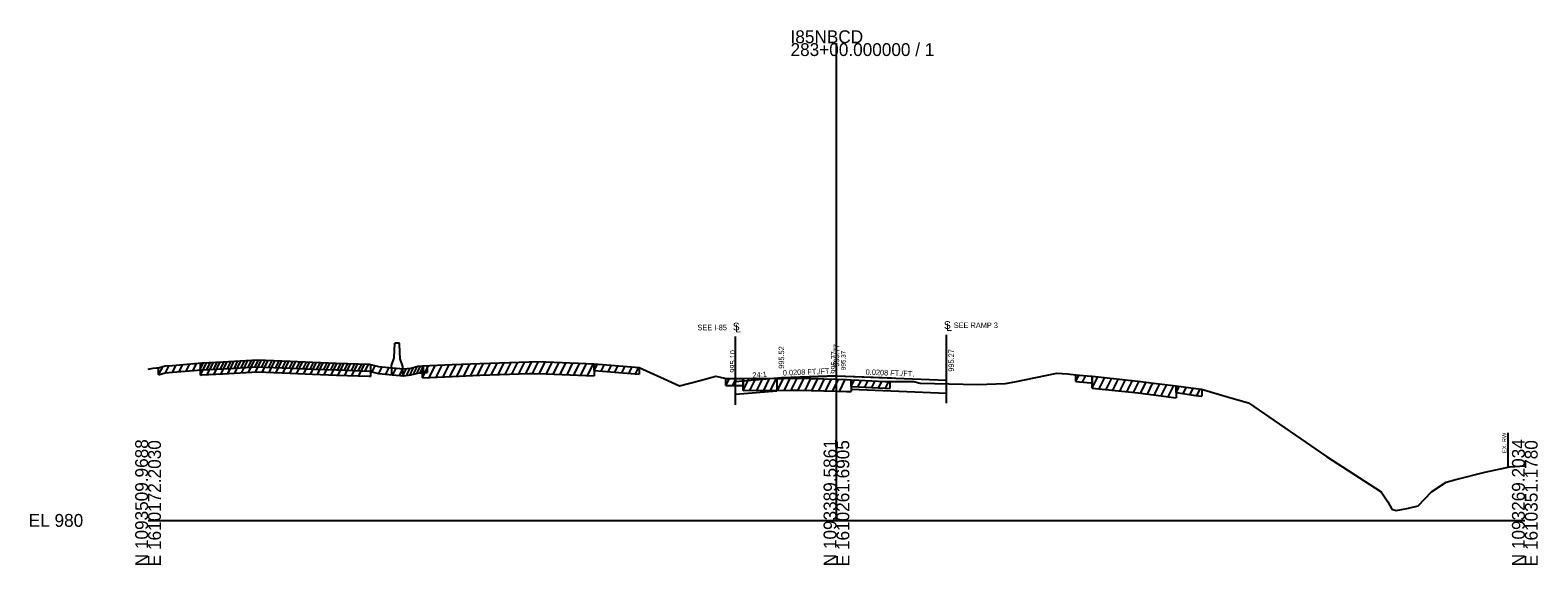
# Model space of a CAD drawing. Extents: x -26 to 1615432, y -20 to 1281970.
# Drawn here: x 974.3 to 1302.8, y 9490.3 to 9606.9 of the extents above; entities that cross this region are included whole.
import ezdxf

# ---------------------------------------------------------------- set-up
doc = ezdxf.new("R2010")
doc.units = 0
for name, color, linetype in [('CLS_MSE_MS_Wall', 7, 'Continuous'), ('CLS_Slope_MSE', 7, 'Continuous'), ('HY_DR_DumbNodes', 7, 'Continuous'), ('RD_EX_Misc', 7, 'Continuous'), ('RD_GPK_XS_Cell', 7, 'Continuous'), ('RD_PD_DR_FlowCtrl', 7, 'Continuous'), ('RD_Sketch1', 7, 'Continuous'), ('RD_XE_Ground', 7, 'Continuous'), ('RD_XS_Base', 7, 'Continuous'), ('RD_XS_ExGround', 7, 'Continuous'), ('RD_XS_ExPaveRet', 7, 'Continuous'), ('RD_XS_MatchLine', 7, 'Continuous'), ('RD_XS_Pave', 7, 'Continuous'), ('RD_XS_PaveShd', 7, 'Continuous'), ('RD_XS_TX_Elev_EX', 7, 'Continuous'), ('RD_XS_TX_Elev_PR', 7, 'Continuous'), ('RD_XS_TX_MatchLine', 7, 'Continuous'), ('RD_XS_TX_ShdSlope', 7, 'Continuous'), ('RD_XS_TX_Slope', 7, 'Continuous')]:
    doc.layers.add(name, color=color, linetype=linetype)

msp = doc.modelspace()

# ---------------------------------------------------------------- linework, layer by layer
at = {"layer": 'CLS_Slope_MSE'}
msp.add_line((1296.33, 9519.09), (1296.33, 9511.57), dxfattribs=at)
at = {"layer": 'HY_DR_DumbNodes'}
for p, q in [((1138, 9531.04), (1150, 9531.54)), ((1150, 9531.54), (1162, 9531.04))]:
    msp.add_line(p, q, dxfattribs=at)
at = {"layer": 'RD_EX_Misc'}
for p, q in [((1097.24, 9532.64), (1097.24, 9534.14)), ((1002.31, 9531.73), (1002.31, 9533.23)), ((1002.31, 9531.73), (1003.75, 9532.16)), ((1003.75, 9532.16), (1005.32, 9532.29)), ((1005.32, 9532.29), (1011.72, 9532.82)), ((1011.72, 9532.82), (1016.31, 9533.06)), ((1016.31, 9533.06), (1023.87, 9533.5)), ((1023.87, 9533.5), (1030.97, 9533.17)), ((1030.97, 9533.17), (1035.84, 9532.96)), ((1035.84, 9532.96), (1041.04, 9532.79)), ((1041.04, 9532.79), (1048.16, 9532.52)), ((1048.16, 9532.52), (1050.23, 9532.02)), ((1050.23, 9532.02), (1053.28, 9531.76)), ((1053.03, 9533.28), (1053.03, 9531.78)), ((1053.03, 9531.78), (1053.28, 9531.76)), ((1053.28, 9531.76), (1055.64, 9531.5)), ((1055.55, 9531.51), (1055.55, 9533.01)), ((1055.55, 9531.51), (1055.64, 9531.5)), ((1055.64, 9531.5), (1057.24, 9531.7)), ((1057.24, 9531.7), (1058.75, 9532.1)), ((1058.75, 9532.1), (1059.79, 9532.18)), ((1059.79, 9533.68), (1059.79, 9532.18)), ((1059.79, 9532.18), (1060.81, 9532.22)), ((1059.79, 9532.18), (1060.05, 9532.19)), ((1060.05, 9532.19), (1060.05, 9533.69)), ((1060.81, 9533.72), (1060.81, 9532.22)), ((1097.24, 9532.64), (1100.85, 9532.35)), ((1100.85, 9532.35), (1107.04, 9531.86)), ((1107.04, 9533.36), (1107.04, 9531.86)), ((1125.93, 9529.41), (1125.93, 9530.91)), ((1129.64, 9530.91), (1129.64, 9529.41)), ((1202.13, 9530.24), (1202.13, 9531.74)), ((1205.76, 9531.44), (1205.76, 9529.94)), ((1125.93, 9529.41), (1127.4, 9529.41)), ((1127.4, 9529.41), (1129.64, 9529.41)), ((1153.19, 9529.16), (1153.19, 9530.66)), ((1153.19, 9529.16), (1154.85, 9529.09)), ((1154.85, 9529.09), (1160.54, 9528.81)), ((1160.54, 9528.81), (1161.67, 9528.76)), ((1161.67, 9530.26), (1161.67, 9528.76)), ((1161.67, 9528.76), (1161.67, 9528.76)), ((1202.13, 9530.24), (1205.41, 9529.97)), ((1205.41, 9529.97), (1205.76, 9529.94)), ((1205.76, 9529.94), (1205.76, 9529.94)), ((1224.05, 9527.85), (1224.05, 9529.35)), ((1224.05, 9527.85), (1228.33, 9527.24)), ((1229.59, 9528.57), (1229.59, 9527.07)), ((1228.33, 9527.24), (1228.86, 9527.17)), ((1228.86, 9527.17), (1229.58, 9527.07)), ((1229.58, 9527.07), (1229.59, 9527.07))]:
    msp.add_line(p, q, dxfattribs=at)
at = {"layer": 'RD_GPK_XS_Cell'}
for p, q in [((1150, 9500), (1150, 9604.02)), ((1000, 9500), (1150, 9500)), ((1150, 9500), (1300, 9500))]:
    msp.add_line(p, q, dxfattribs=at)
at = {"layer": 'RD_PD_DR_FlowCtrl'}
for p, q in [((1138, 9531.04), (1150, 9531.54)), ((1150, 9531.54), (1162, 9531.04))]:
    msp.add_line(p, q, dxfattribs=at)
at = {"layer": 'RD_Sketch1'}
for p, q in [((1008.31, 9532.54), (1009.09, 9534.1)), ((1009.81, 9532.66), (1010.59, 9534.23)), ((1011.31, 9532.79), (1012.09, 9534.34)), ((1012.81, 9532.88), (1013.58, 9534.42)), ((1014.31, 9532.96), (1015.08, 9534.5)), ((1015.81, 9533.04), (1016.58, 9534.58)), ((1017.31, 9533.12), (1018.09, 9534.67)), ((1018.81, 9533.21), (1019.59, 9534.75)), ((1020.31, 9533.3), (1021.09, 9534.84)), ((1021.81, 9533.38), (1022.59, 9534.93)), ((1023.31, 9533.47), (1024.07, 9534.99)), ((1024.81, 9533.46), (1025.55, 9534.92)), ((1026.31, 9533.39), (1027.05, 9534.85)), ((1027.81, 9533.32), (1028.55, 9534.78)), ((1029.31, 9533.25), (1030.05, 9534.71)), ((1030.81, 9533.18), (1031.55, 9534.65)), ((1032.31, 9533.11), (1033.05, 9534.58)), ((1033.81, 9533.05), (1034.55, 9534.52)), ((1035.31, 9532.98), (1036.05, 9534.45)), ((1036.81, 9532.93), (1037.55, 9534.4)), ((1038.31, 9532.88), (1039.05, 9534.35)), ((1039.81, 9532.83), (1040.55, 9534.3)), ((1041.31, 9532.78), (1042.05, 9534.25)), ((1042.81, 9532.72), (1043.55, 9534.19)), ((1044.31, 9532.66), (1045.05, 9534.13)), ((1045.81, 9532.61), (1046.55, 9534.08)), ((1047.31, 9532.55), (1048.05, 9534.02)), ((1097.24, 9532.64), (1097.96, 9534.08)), ((1002.31, 9531.73), (1003.19, 9533.49)), ((1003.81, 9532.16), (1004.6, 9533.73)), ((1005.31, 9532.29), (1006.09, 9533.86)), ((1006.81, 9532.42), (1007.59, 9533.98)), ((1048.81, 9532.36), (1049.48, 9533.7)), ((1050.31, 9532.01), (1051.03, 9533.45)), ((1051.81, 9531.88), (1052.53, 9533.32)), ((1053.31, 9531.76), (1054.03, 9533.18)), ((1054.81, 9531.59), (1055.53, 9533.01)), ((1055.55, 9531.51), (1056.34, 9533.09)), ((1056.31, 9531.58), (1057.11, 9533.18)), ((1057.05, 9531.67), (1057.9, 9533.37)), ((1057.81, 9531.85), (1058.68, 9533.58)), ((1058.55, 9532.04), (1059.35, 9533.64)), ((1059.31, 9532.14), (1060.09, 9533.69)), ((1098.74, 9532.52), (1099.46, 9533.96)), ((1100.24, 9532.4), (1100.96, 9533.85)), ((1101.74, 9532.28), (1102.46, 9533.73)), ((1103.24, 9532.16), (1103.96, 9533.61)), ((1104.74, 9532.04), (1105.46, 9533.49)), ((1106.24, 9531.93), (1106.96, 9533.37)), ((1125.93, 9529.41), (1126.68, 9530.91)), ((1127.43, 9529.41), (1128.18, 9530.91)), ((1202.13, 9530.24), (1202.85, 9531.68)), ((1203.63, 9530.12), (1204.35, 9531.56)), ((1153.19, 9529.16), (1153.93, 9530.63)), ((1154.69, 9529.1), (1155.43, 9530.57)), ((1156.19, 9529.03), (1156.93, 9530.49)), ((1157.69, 9528.95), (1158.43, 9530.42)), ((1159.2, 9528.88), (1159.93, 9530.34)), ((1160.7, 9528.8), (1161.43, 9530.27)), ((1224.05, 9527.85), (1224.75, 9529.25)), ((1225.55, 9527.64), (1226.25, 9529.04)), ((1227.05, 9527.42), (1227.75, 9528.82)), ((1228.55, 9527.21), (1229.26, 9528.62))]:
    msp.add_line(p, q, dxfattribs=at)
at = {"layer": 'RD_XE_Ground'}
for p, q in [((1053.62, 9535.45), (1053.78, 9538.61)), ((1054.8, 9538.61), (1053.78, 9538.61)), ((1054.8, 9538.35), (1054.8, 9538.61)), ((1054.96, 9535.18), (1054.8, 9538.35)), ((1053.03, 9533.78), (1053.62, 9535.45)), ((1055.55, 9533.51), (1054.96, 9535.18)), ((1053.03, 9533.28), (1053.03, 9533.78)), ((1055.55, 9533.01), (1055.55, 9533.51))]:
    msp.add_line(p, q, dxfattribs=at)
at = {"layer": 'RD_XS_Base'}
for p, q in [((1137.02, 9530.95), (1138, 9530.96)), ((1137.02, 9530.95), (1137.02, 9528.18)), ((1138, 9530.96), (1139.99, 9530.97)), ((1139.99, 9530.97), (1141.7, 9530.97)), ((1141.7, 9530.97), (1150, 9530.75)), ((1150, 9530.75), (1152.18, 9530.69)), ((1128, 9527.43), (1128, 9530.2)), ((1137.02, 9528.18), (1128, 9527.43)), ((1152.18, 9530.69), (1153.19, 9530.66)), ((1153.19, 9530.66), (1153.19, 9530.66)), ((1153.19, 9530.66), (1153.19, 9528.63)), ((1153.19, 9528.63), (1174, 9527.76)), ((1174, 9527.76), (1174, 9529.76))]:
    msp.add_line(p, q, dxfattribs=at)
at = {"layer": 'RD_XS_ExGround'}
msp.add_lwpolyline([(1000, 9532.93), (1001.13, 9533.15), (1001.82, 9533.23), (1002.31, 9533.23), (1003.75, 9533.66), (1005.32, 9533.79), (1011.72, 9534.32), (1016.31, 9534.56), (1023.87, 9535), (1030.97, 9534.67), (1035.84, 9534.46), (1041.04, 9534.29), (1048.16, 9534.02), (1050.23, 9533.52), (1053.28, 9533.26), (1055.64, 9533), (1057.24, 9533.2), (1058.75, 9533.6), (1059.79, 9533.68), (1066.29, 9533.96), (1072.29, 9534.22), (1083.06, 9534.59), (1084.21, 9534.63), (1086.72, 9534.53), (1097.24, 9534.14), (1100.85, 9533.85), (1107.04, 9533.36), (1114.03, 9530.16), (1115.77, 9529.35), (1119.99, 9530.45), (1123.7, 9531.43), (1124.38, 9531.28), (1125.93, 9530.91), (1127.4, 9530.91), (1129.64, 9530.91), (1139.99, 9530.97), (1141.7, 9530.97), (1150, 9530.75), (1152.18, 9530.69), (1153.19, 9530.66), (1154.85, 9530.59), (1160.54, 9530.31), (1161.67, 9530.26), (1162.08, 9530.26), (1166.89, 9530.3), (1168.21, 9529.9), (1180.71, 9529.6), (1186.87, 9529.82), (1188.86, 9530.21), (1198.03, 9532.11), (1200.32, 9531.95), (1202.13, 9531.74), (1205.41, 9531.47), (1205.76, 9531.44), (1213.62, 9530.59), (1215.77, 9530.37), (1219.07, 9529.94), (1224.05, 9529.35), (1228.33, 9528.74), (1228.86, 9528.67), (1229.58, 9528.57), (1235.41, 9526.85), (1239.77, 9525.6), (1256.77, 9513.94), (1268.71, 9506.24), (1270.12, 9504.02), (1271, 9502.48), (1271.94, 9502.19), (1273.13, 9502.37), (1274.63, 9502.67), (1276.75, 9503.2), (1279.67, 9506.19), (1282.84, 9508.36), (1284.94, 9508.9), (1291.29, 9510.54), (1296.76, 9511.66), (1300, 9511.92)], dxfattribs=at)
at = {"layer": 'RD_XS_ExPaveRet'}
for p, q in [((1011.41, 9531.69), (1012.75, 9534.37)), ((1011.41, 9531.69), (1011.41, 9534.29)), ((1012.91, 9531.78), (1014.24, 9534.45)), ((1014.41, 9531.86), (1015.74, 9534.53)), ((1015.91, 9531.94), (1017.24, 9534.62)), ((1017.41, 9532.03), (1018.75, 9534.71)), ((1018.91, 9532.11), (1020.25, 9534.79)), ((1020.41, 9532.2), (1021.75, 9534.88)), ((1021.91, 9532.29), (1023.25, 9534.97)), ((1023.41, 9532.38), (1024.7, 9534.96)), ((1024.91, 9532.35), (1026.18, 9534.89)), ((1026.41, 9532.28), (1027.68, 9534.82)), ((1027.91, 9532.21), (1029.18, 9534.75)), ((1029.41, 9532.14), (1030.68, 9534.68)), ((1030.91, 9532.07), (1032.18, 9534.62)), ((1032.41, 9532.01), (1033.68, 9534.55)), ((1033.91, 9531.94), (1035.18, 9534.49)), ((1035.41, 9531.88), (1036.68, 9534.43)), ((1036.91, 9531.82), (1038.19, 9534.38)), ((1038.41, 9531.77), (1039.69, 9534.33)), ((1039.91, 9531.72), (1041.19, 9534.28)), ((1041.41, 9531.67), (1042.68, 9534.22)), ((1042.91, 9531.62), (1044.18, 9534.17)), ((1044.41, 9531.56), (1045.68, 9534.11)), ((1045.91, 9531.5), (1047.18, 9534.05)), ((1067.29, 9531.4), (1068.62, 9534.06)), ((1068.79, 9531.47), (1070.12, 9534.12)), ((1070.29, 9531.53), (1071.62, 9534.19)), ((1071.79, 9531.6), (1073.11, 9534.25)), ((1073.29, 9531.65), (1074.61, 9534.3)), ((1074.79, 9531.7), (1076.11, 9534.35)), ((1076.29, 9531.76), (1077.61, 9534.4)), ((1077.79, 9531.81), (1079.11, 9534.45)), ((1079.29, 9531.86), (1080.61, 9534.5)), ((1080.79, 9531.91), (1082.11, 9534.56)), ((1082.29, 9531.96), (1083.61, 9534.61)), ((1083.79, 9532.01), (1085.08, 9534.6)), ((1085.29, 9531.99), (1086.56, 9534.54)), ((1086.79, 9531.93), (1088.06, 9534.48)), ((1088.29, 9531.88), (1089.56, 9534.43)), ((1089.79, 9531.82), (1091.06, 9534.37)), ((1091.29, 9531.76), (1092.56, 9534.31)), ((1092.79, 9531.71), (1094.06, 9534.26)), ((1094.29, 9531.65), (1095.56, 9534.2)), ((1095.79, 9531.59), (1097.06, 9534.14)), ((1097.24, 9534.14), (1097.24, 9531.54)), ((1011.41, 9531.69), (1011.72, 9531.72)), ((1011.72, 9531.72), (1016.31, 9531.96)), ((1016.31, 9531.96), (1023.87, 9532.4)), ((1023.87, 9532.4), (1030.97, 9532.07)), ((1030.97, 9532.07), (1035.84, 9531.86)), ((1035.84, 9531.86), (1041.04, 9531.69)), ((1041.04, 9531.69), (1048.16, 9531.42)), ((1048.16, 9531.42), (1048.49, 9531.34)), ((1048.49, 9533.94), (1048.49, 9531.34)), ((1059.79, 9531.08), (1061.12, 9533.74)), ((1059.79, 9531.08), (1059.79, 9533.68)), ((1059.79, 9531.08), (1066.29, 9531.36)), ((1061.29, 9531.14), (1062.62, 9533.8)), ((1062.79, 9531.21), (1064.12, 9533.86)), ((1064.29, 9531.27), (1065.62, 9533.93)), ((1065.79, 9531.34), (1067.12, 9533.99)), ((1066.29, 9531.36), (1072.29, 9531.62)), ((1072.29, 9531.62), (1083.06, 9531.99)), ((1083.06, 9531.99), (1084.21, 9532.03)), ((1084.21, 9532.03), (1086.72, 9531.93)), ((1086.72, 9531.93), (1097.24, 9531.54)), ((1129.64, 9528.31), (1130.95, 9530.92)), ((1129.64, 9528.31), (1129.64, 9530.91)), ((1131.14, 9528.32), (1132.45, 9530.93)), ((1132.64, 9528.33), (1133.95, 9530.94)), ((1134.15, 9528.34), (1135.45, 9530.95)), ((1135.65, 9528.35), (1136.95, 9530.95)), ((1137.15, 9528.36), (1138.45, 9530.96)), ((1138.65, 9528.36), (1139.95, 9530.97)), ((1140.15, 9528.37), (1141.44, 9530.97)), ((1141.65, 9528.37), (1142.93, 9530.94)), ((1143.15, 9528.33), (1144.43, 9530.9)), ((1144.65, 9528.29), (1145.93, 9530.86)), ((1146.15, 9528.25), (1147.43, 9530.82)), ((1147.65, 9528.21), (1148.93, 9530.78)), ((1149.15, 9528.17), (1150.43, 9530.74)), ((1205.76, 9528.84), (1205.76, 9531.44)), ((1205.76, 9528.84), (1206.99, 9531.31)), ((1207.26, 9528.68), (1208.49, 9531.14)), ((1208.76, 9528.52), (1209.99, 9530.98)), ((1210.26, 9528.35), (1211.49, 9530.82)), ((1129.64, 9528.31), (1139.99, 9528.37)), ((1139.99, 9528.37), (1141.7, 9528.37)), ((1141.7, 9528.37), (1150, 9528.15)), ((1150, 9528.15), (1152.18, 9528.09)), ((1150.65, 9528.13), (1151.93, 9530.7)), ((1152.18, 9528.09), (1153.19, 9528.06)), ((1153.19, 9530.66), (1153.19, 9528.06)), ((1153.19, 9528.06), (1153.19, 9528.06)), ((1205.76, 9528.84), (1213.62, 9527.99)), ((1211.76, 9528.19), (1212.99, 9530.66)), ((1213.26, 9528.03), (1214.5, 9530.5)), ((1213.62, 9527.99), (1215.77, 9527.77)), ((1214.76, 9527.87), (1215.99, 9530.34)), ((1215.77, 9527.77), (1219.07, 9527.34)), ((1216.26, 9527.7), (1217.48, 9530.14)), ((1217.76, 9527.51), (1218.98, 9529.95)), ((1219.26, 9527.31), (1220.49, 9529.77)), ((1220.76, 9527.14), (1221.99, 9529.59)), ((1222.26, 9526.96), (1223.49, 9529.42)), ((1224.05, 9529.35), (1224.05, 9526.75)), ((1219.07, 9527.34), (1224.05, 9526.75)), ((1224.05, 9526.75), (1224.05, 9526.75))]:
    msp.add_line(p, q, dxfattribs=at)
at = {"layer": 'RD_XS_MatchLine'}
for p, q in [((1128, 9530.91), (1128, 9530.2)), ((1174, 9529.76), (1174, 9530.54))]:
    msp.add_line(p, q, dxfattribs=at)
at = {"layer": 'RD_XS_Pave'}
for q in [(1138, 9531.04), (1174, 9530.54)]:
    msp.add_line((1150, 9531.54), q, dxfattribs=at)
at = {"layer": 'RD_XS_PaveShd'}
msp.add_line((1138, 9531.04), (1128, 9530.2), dxfattribs=at)
at = {"layer": 'RD_XS_TX_MatchLine'}
for p, q in [((1128, 9530.2), (1128, 9540.09)), ((1174, 9530.54), (1174, 9540.42)), ((1128, 9525.2), (1128, 9530.2)), ((1174, 9525.54), (1174, 9530.54))]:
    msp.add_line(p, q, dxfattribs=at)

# ---------------------------------------------------------------- texts
at = {"layer": 'CLS_MSE_MS_Wall'}
for s, p in [('SEE I-85', (1119.71, 9541.44)), ('SEE RAMP 3', (1175.56, 9541.93))]:
    msp.add_text(s, height=1.2, dxfattribs=at).set_placement(p)
at = {"layer": 'CLS_Slope_MSE'}
msp.add_text('EX. RW', height=0.9, rotation=90, dxfattribs=at).set_placement((1295.97, 9514.69))
at = {"layer": 'HY_DR_DumbNodes'}
msp.add_text(' 995.77', height=1.2, rotation=90, dxfattribs=at).set_placement((1150, 9531.54))
at = {"layer": 'RD_GPK_XS_Cell'}
for s, p in [('I85NBCD', (1140, 9604.02)), ('283+00.000000 / 1', (1140, 9601.22)), ('EL 980', (974, 9498.6))]:
    msp.add_text(s, height=2.8, dxfattribs=at).set_placement(p)
for s, p in [('N 1093509.9688', (1000, 9490)), ('E 1610172.2030', (1002.8, 9490)), ('N 1093389.5861', (1150, 9490)), ('E 1610261.6905', (1152.8, 9490)), ('N 1093269.2034', (1300, 9490)), ('E 1610351.1780', (1302.8, 9490))]:
    msp.add_text(s, height=2.8, rotation=90, dxfattribs=at).set_placement(p)
at = {"layer": 'RD_PD_DR_FlowCtrl'}
msp.add_text(' 995.77', height=1.2, rotation=90, dxfattribs=at).set_placement((1150, 9531.54))
at = {"layer": 'RD_XS_TX_Elev_EX'}
msp.add_text('995.37', height=1, rotation=90, dxfattribs=at).set_placement((1152, 9532.75))
at = {"layer": 'RD_XS_TX_Elev_PR'}
for s, p in [('995.52', (1138.6, 9533.04)), ('995.77', (1150.6, 9533.54)), ('995.10', (1128, 9532.2)), ('995.27', (1175.61, 9532.41))]:
    msp.add_text(s, height=1.2, rotation=90, dxfattribs=at).set_placement(p)
at = {"layer": 'RD_XS_TX_MatchLine'}
for s, p in [('S', (1127.42, 9541.41)), ('L', (1127.93, 9540.97)), ('S', (1173.42, 9541.74)), ('L', (1173.93, 9541.3))]:
    msp.add_text(s, height=1.68, dxfattribs=at).set_placement(p)
at = {"layer": 'RD_XS_TX_ShdSlope'}
msp.add_text('24:1', height=1.2, rotation=4.7636, dxfattribs=at).set_placement((1131.75, 9531.02))
at = {"layer": 'RD_XS_TX_Slope'}
for rotation, p in [(2.3859, (1138.34, 9531.55)), (357.6141, (1156.35, 9531.77))]:
    msp.add_text('0.0208 FT./FT.', height=1.2, rotation=rotation, dxfattribs=at).set_placement(p)

doc.saveas('drawing.dxf')
